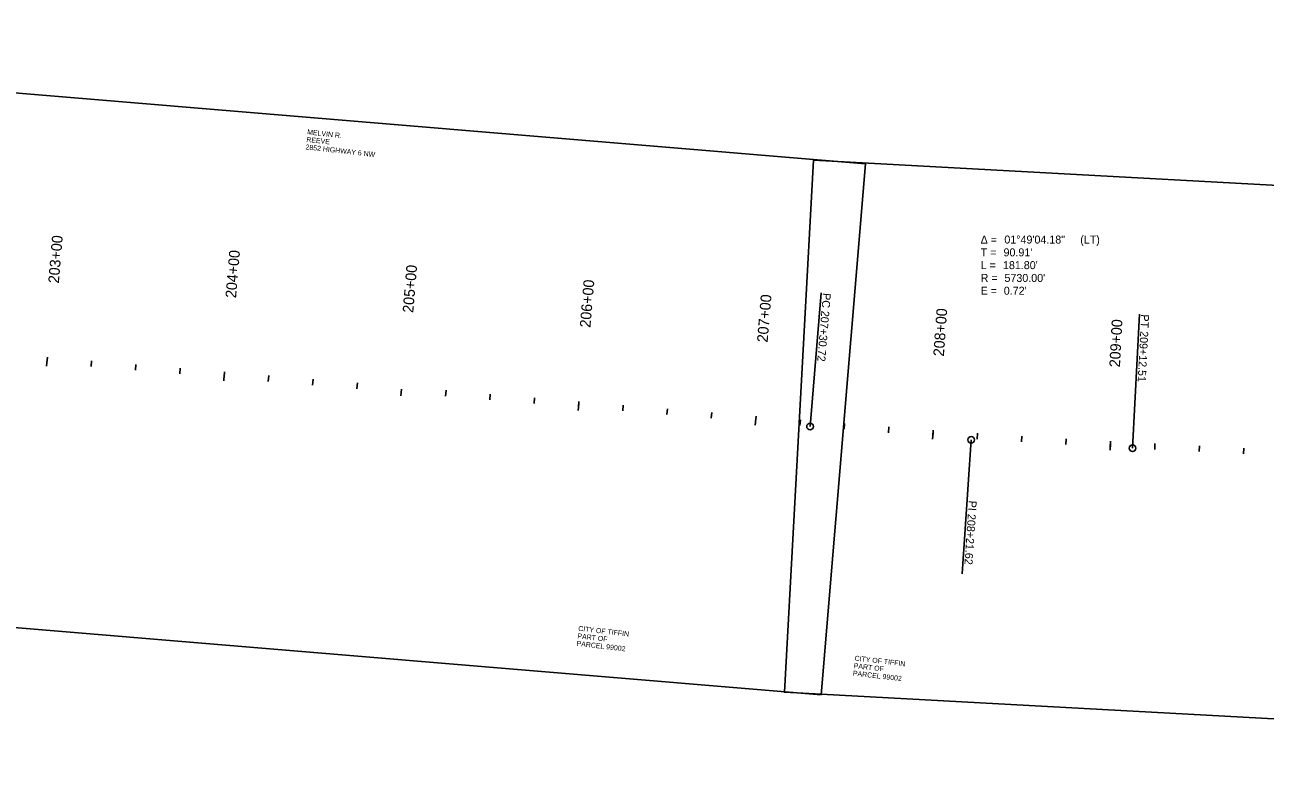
# Model space of a CAD drawing. Extents: x 20499788 to 20505371, y 7953467 to 7954209.
# Drawn here: x 20503988 to 20504686, y 7953467 to 7953894 of the extents above; entities that cross this region are included whole.
import ezdxf

# ---------------------------------------------------------------- set-up
doc = ezdxf.new("R2010")
doc.units = 0
for name, color, linetype in [('NamedBoundary', 7, 'Continuous'), ('Text', 7, 'Continuous'), ('TextAlignment', 7, 'Continuous'), ('TextAlignmentLrg', 7, 'Continuous'), ('TextAlignmentSml', 7, 'Continuous')]:
    doc.layers.add(name, color=color, linetype=linetype)

msp = doc.modelspace()

# ---------------------------------------------------------------- linework, layer by layer
at = {"layer": 'NamedBoundary'}
for points in [[(20503523.55, 7953893.55), (20503498.6, 7953594.59), (20504435.84, 7953516.39), (20504460.79, 7953815.35)], [(20504431.55, 7953817.36), (20504415.22, 7953517.81), (20505354.3, 7953466.63), (20505370.62, 7953766.18)]]:
    msp.add_lwpolyline(points, close=True, dxfattribs=at)
at = {"layer": 'TextAlignment'}
for p, q in [((20504429.6, 7953667.42), (20504435.88, 7953742.76)), ((20504435.88, 7953742.76), (20504435.88, 7953742.76)), ((20504610.98, 7953655.19), (20504614.87, 7953730.69)), ((20504614.87, 7953730.69), (20504614.87, 7953730.69)), ((20504520.19, 7953659.87), (20504515.1, 7953584.44)), ((20504515.1, 7953584.44), (20504515.1, 7953584.44))]:
    msp.add_line(p, q, dxfattribs=at)
for centre in [(20504429.6, 7953667.42), (20504520.19, 7953659.87), (20504610.98, 7953655.19)]:
    msp.add_circle(centre, 1.87, dxfattribs=at)
at = {"layer": 'TextAlignmentLrg'}
for p, q in [((20504000.37, 7953703.24), (20504000.65, 7953706.51)), ((20504100.03, 7953694.92), (20504100.3, 7953698.19)), ((20504199.83, 7953688.44), (20504199.53, 7953684.78)), ((20504299.33, 7953678.29), (20504299.61, 7953681.56)), ((20504398.99, 7953669.98), (20504399.26, 7953673.24)), ((20504498.68, 7953662.08), (20504498.91, 7953665.35)), ((20504598.48, 7953655.84), (20504598.66, 7953659.12))]:
    msp.add_line(p, q, dxfattribs=at)
at = {"layer": 'TextAlignmentSml'}
for p, q in [((20504000.53, 7953705.07), (20504000.22, 7953701.41)), ((20504025.29, 7953701.16), (20504025.56, 7953704.43)), ((20504050.2, 7953699.08), (20504050.47, 7953702.35)), ((20504075.11, 7953697), (20504075.39, 7953700.27)), ((20504100.18, 7953696.75), (20504099.87, 7953693.09)), ((20504124.94, 7953692.85), (20504125.21, 7953696.11)), ((20504149.85, 7953690.77), (20504150.13, 7953694.03)), ((20504174.77, 7953688.69), (20504175.04, 7953691.95)), ((20504199.83, 7953688.44), (20504199.53, 7953684.78)), ((20504224.59, 7953684.53), (20504224.87, 7953687.79)), ((20504249.51, 7953682.45), (20504249.78, 7953685.71)), ((20504274.42, 7953680.37), (20504274.69, 7953683.64)), ((20504299.49, 7953680.12), (20504299.18, 7953676.46)), ((20504324.25, 7953676.21), (20504324.52, 7953679.48)), ((20504349.16, 7953674.14), (20504349.43, 7953677.4)), ((20504374.08, 7953672.06), (20504374.35, 7953675.32)), ((20504399.14, 7953671.81), (20504398.84, 7953668.15)), ((20504423.9, 7953667.9), (20504424.17, 7953671.16)), ((20504448.82, 7953665.85), (20504449.08, 7953669.12)), ((20504473.74, 7953663.91), (20504473.99, 7953667.18)), ((20504498.81, 7953663.91), (20504498.54, 7953660.25)), ((20504523.62, 7953660.36), (20504523.83, 7953663.63)), ((20504548.56, 7953658.75), (20504548.77, 7953662.02)), ((20504573.52, 7953657.24), (20504573.71, 7953660.51)), ((20504598.58, 7953657.68), (20504598.38, 7953654.01)), ((20504623.45, 7953654.54), (20504623.61, 7953657.82)), ((20504648.41, 7953653.26), (20504648.58, 7953656.53)), ((20504673.38, 7953651.97), (20504673.55, 7953655.24))]:
    msp.add_line(p, q, dxfattribs=at)

# ---------------------------------------------------------------- texts
at = {"layer": 'Text'}
for s, height, rotation, p in [('MELVIN R. ', 2.835, 353.65909, (20504146.68, 7953831.89)), ('REEVE', 2.835, 353.65909, (20504146.21, 7953827.67)), ('2852 HIGHWAY 6 NW', 2.8346, 353.65909, (20504145.74, 7953823.44)), ('CITY OF TIFFIN', 2.8346, 353.49015, (20504299.14, 7953552.43)), ('PART OF ', 2.835, 353.49015, (20504298.66, 7953548.21)), ('PARCEL 99002', 2.8346, 353.49015, (20504298.18, 7953543.98)), ('PART OF ', 2.835, 353.49015, (20504454.07, 7953531.45)), ('CITY OF TIFFIN', 2.8346, 353.49015, (20504454.55, 7953535.67)), ('PARCEL 99002', 2.8346, 353.49015, (20504453.59, 7953527.23))]:
    msp.add_text(s, height=height, rotation=rotation, dxfattribs=at).set_placement(p)
at = {"layer": 'TextAlignment'}
for s, p in [('Δ = ', (20504525.57, 7953770.41)), ('01°49\'04.18"', (20504538.89, 7953770.41)), (' (LT)', (20504579.9, 7953770.41)), ('T = ', (20504525.57, 7953763.21)), ("90.91'", (20504538.44, 7953763.21)), ('L = ', (20504525.57, 7953756.01)), ("181.80'", (20504538.11, 7953756.01)), ('R = ', (20504525.57, 7953748.81)), ("5730.00'", (20504538.96, 7953748.81)), ('E = ', (20504525.57, 7953741.61)), ("0.72'", (20504538.57, 7953741.61))]:
    msp.add_text(s, height=4.5, dxfattribs=at).set_placement(p)
for s, rotation, p in [('PC', 265.23083, (20504436.87, 7953742.68)), ('207+30.72', 265.23083, (20504436.04, 7953732.72)), ('PT', 267.04866, (20504615.85, 7953730.64)), ('209+12.51', 267.04866, (20504615.37, 7953721.19)), ('PI ', 266.13975, (20504518.88, 7953625.8)), ('208+21.62', 266.13975, (20504518.38, 7953618.31))]:
    msp.add_text(s, height=4.5, rotation=rotation, dxfattribs=at).set_placement(p)
at = {"layer": 'TextAlignmentLrg'}
msp.add_text('205+00', height=6.012, rotation=85.22957, dxfattribs=at).set_placement((20504206.42, 7953731.2))
at = {"layer": 'TextAlignmentSml'}
for s, rotation, p in [('203+00', 85.22957, (20504007.11, 7953747.84)), ('204+00', 85.22957, (20504106.77, 7953739.52)), ('205+00', 85.22957, (20504206.42, 7953731.2)), ('206+00', 85.23083, (20504306.07, 7953722.89)), ('207+00', 85.23083, (20504405.73, 7953714.57)), ('208+00', 85.92361, (20504504.87, 7953706.75)), ('209+00', 86.92354, (20504603.9, 7953700.62))]:
    msp.add_text(s, height=6.012, rotation=rotation, dxfattribs=at).set_placement(p)

doc.saveas('drawing.dxf')
